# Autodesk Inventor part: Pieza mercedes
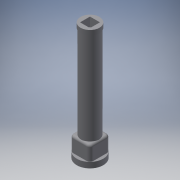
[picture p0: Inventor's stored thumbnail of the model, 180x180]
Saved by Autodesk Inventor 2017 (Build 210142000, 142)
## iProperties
Created: 2017-03
Part Number: Pieza mercedes
Document SubType Name: Modeling
Designer: Ricardo
Density: 1 g/cm^3
Material: Genérico
Appearance: Valor por defecto
Author: Ricardo
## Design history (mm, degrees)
sketch "Boceto1"
  geometry: C1 r 4.2 at (0, 0); 1 further point
  constraints: 1 centre point, 1 coincident
  dimensions: "d0" = 8.4 diameter of C1
extrude "Extrusión1" new body sketch "Boceto1" distance "d1" = 2; taper "d2" = 0 deg
sketch "Boceto2"
  geometry: C1 r 4.2 at (0, 0) reference; C2 r 3.95 at (0, 0)
  constraints: 1 centre point, 1 coincident
  dimensions: "d3" = 7.9 diameter of C2
extrude "Extrusión2" join sketch "Boceto2" distance "d4" = 41; taper "d5" = 0 deg
sketch "Boceto3"
  geometry: L1 (4.5, 4.5)-(4.5, -4.5); L2 (4.5, -4.5)-(-4.5, -4.5); L3 (-4.5, -4.5)-(-4.5, 4.5); L4 (-4.5, 4.5)-(4.5, 4.5); C1 r 3.95 at (0, 0) reference; 1 further point
  constraints: 8 end point, 1 coincident, 9 other
  dimensions: "d6" = 9 distance of L3.end L1.start
extrude "Extrusión3" join sketch "Boceto3" distance "d7" = 6.5; taper "d8" = 0 deg
sketch "Boceto4"
  geometry: C1 r 5.85 at (0, 0); 1 further point
  constraints: 1 centre point, 1 coincident
  dimensions: "d9" = 11.7 diameter of C1
extrude "Extrusión4" join sketch "Boceto4" distance "d10" = 2.5; taper "d11" = 0 deg
fillet "Empalme1" dims "d12" = 1.5
sketch "Boceto5"
  geometry: L1 (3.55, 3.55)-(3.55, -3.55); L2 (3.55, -3.55)-(-3.55, -3.55); L3 (-3.55, -3.55)-(-3.55, 3.55); L4 (-3.55, 3.55)-(3.55, 3.55); C1 r 5.85 at (0, 0) reference; 1 further point
  constraints: 8 end point, 1 coincident, 9 other
  dimensions: "d13" = 7.1 distance of L3.end L1.start
extrude "Extrusión5" cut sketch "Boceto5" distance "d14" = 7.5; taper "d15" = 0 deg
sketch "Boceto6"
  geometry: L1 (2.2, 2.2)-(2.2, -2.2); L2 (2.2, -2.2)-(-2.2, -2.2); L3 (-2.2, -2.2)-(-2.2, 2.2); L4 (-2.2, 2.2)-(2.2, 2.2); C1 r 4.2 at (0, 0) reference; 1 further point
  constraints: 8 end point, 1 coincident, 9 other
  dimensions: "d16" = 4.4 distance of L3.end L1.start
extrude "Extrusión6" cut sketch "Boceto6" distance "d17" = 4; taper "d18" = 0 deg
fillet "Empalme2" dims "d19" = 1
sketch "Boceto7"
  geometry: 2 further points
  constraints: 1 coincident
hole "Agujero1" sketch "Boceto7" at (0, 0) diameter "d20" = 2.9; stored, may be unused: countersink angle "d24" = 90 deg, drill point angle "d26" = 118 deg; dims "d21" = 6, "d22" = 4, "d23" = 2, "d25" = 25
node "Sólido1"
